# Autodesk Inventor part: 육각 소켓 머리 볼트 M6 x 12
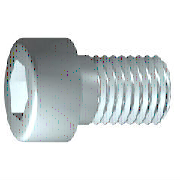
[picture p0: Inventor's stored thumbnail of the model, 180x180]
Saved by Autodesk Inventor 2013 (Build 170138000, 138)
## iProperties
IsCustomPart: 1
Created: 2012-02
Part Number: 육각 소켓 머리 볼트 M6 x 12
Material: 강철, 연강
Description: 원통형 머리 캡 나사
Document SubType Name: Modeling
Standard: JIS B 1176
Designer: mdu-01
Standards Organization: JIS
Language: ko-KR
Size Designation: M6 x 12
Categories: <MemberInstance><Categories><Category DisplayName="조임쇠" InternalName="e4da775c-781d-43d5-af7c-5136215cf5a6" Mnemonic="FSTN"><Category DisplayName="볼트" InternalN
Density: 1 g/cm^3
Author: mdu-01
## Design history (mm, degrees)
sketch "스케치1"
  geometry: L1 (-1.333, 0)-(12, 0); L2 (12, 0)-(12, 3); L3 (12, 3)-(2.5, 3); L4 (2.5, 3)-(1.886, 3); L5 (1.886, 3)-(0, 3); L6 (0, 3)-(0, 5); L7 (0, 5)-(-6, 5); L8 (-6, 5)-(-6, 2.887); L9 (-6, 2.887)-(-3, 2.887); L10 (-3, 2.887)-(-1.333, 0); L11 (-9.6, 0)-(15.6, 0) reference; L12 (0, -1)-(0, 6) reference; L13 (2.5, 3)-(0, 3)
  constraints: 22 end point, 6 parallel, 2 collinear, 2 perpendicular, 1 horizontal, 1 point on line
  dimensions: "d1" = 9.5 distance from line of L3.end L2 (= GEL); "d2" = 0.61355 distance of L4.end L3.end (computed from GAL); "d3" = 6 distance between parallel lines of L8 L6 (= KOH); "d4" = 3 distance of L8.end L9.end (= INTI); "d5" = 60 deg angle of L10 L1; "d6" = 6 diameter of L3 L1 (= GD); "d7" = 6 diameter of L5 L1 (= BDM); "d8" = 5.7735 diameter of L9 L1 (= 1.1547 x SW); "d9" = 10 diameter of L7 L1 (= KOD); "d26" = 12 distance between parallel lines of L12 L2 (= NLG)
revolve "본체" sketch "스케치1" stored, may be unused: angle "d10" = 90 deg
sketch "스케치2"
  geometry: L1 (0, -7)-(0, 7) reference; L2 (-7, 0)-(7, 0) reference; L3 (2.887, 0)-(1.443, -2.5); L4 (1.443, -2.5)-(-1.443, -2.5); L5 (-1.443, -2.5)-(-2.887, 0); L6 (-2.887, 0)-(-1.443, 2.5); L7 (-1.443, 2.5)-(1.443, 2.5); L8 (1.443, 2.5)-(2.887, 0); 2 further points
  constraints: 12 end point, 1 coincident, 1 horizontal alignment, 1 point on line, 12 other
extrude "슬롯" join sketch "스케치2" stored distance "d11" = 10; taper "d12" = 0 deg
workplane "Work Plane1"
fillet "Fillet2" dims "d30" = 0.1 (= R)
body "Solid1"
fillet "모깎기1" dims "d17" = 0.6 (= RR)
feature "스레드" dims "d13" = 9.5 (= GEL), "d14" = 0
chamfer "모따기1" distance "d15" = 0.61345 (= -0.5 x SPD + 0.5 x GD); stored, may be unused: second distance "d16" = 0.61345 (= GUL), angle "d27" = 45 deg
other parameters: "GD" = 6 (= NND) [user parameter; used in 2 equation terms], "NLG" = 12 [user parameter; used in 1 equation term], "GEL" = 9.5 [user parameter; used in 2 equation terms], "KOD" = 10 [user parameter; used in 1 equation term], "KOH" = 6 [user parameter; used in 1 equation term], "INTI" = 3 [user parameter; used in 1 equation term], "GAL" = 0.61345 (= 0.61345 x PTC) [user parameter; used in 1 equation term], "GUL" = 0.61345 (= 0.61345 x PTC) [user parameter; used in 1 equation term], "BDM" = 6 (= NND) [user parameter; used in 1 equation term], "SW" = 5 [user parameter; used in 2 equation terms], "RR" = 0.6 [user parameter; used in 1 equation term], "SPD" = 4.7731 (= NND - 1.2269 x PTC) [user parameter; used in 1 equation term], "d19" = 0, "d28" = 0, "d29" = 0, "R" = 0.1 [user parameter; used in 1 equation term], "PHH" = 0.25 [user parameter], "GD1" = 4.7731 (= THREADDIA - 1.2269 x PTC) [user parameter], "THREADDIA" = 6 [user parameter; used in 1 equation term], "FAWI" = 45 deg [user parameter], "PTC" = 1 [user parameter; used in 5 equation terms], "NND" = 6 [user parameter; used in 3 equation terms], "TOA" = 30 deg [user parameter], "E0" = 5.775 (= 1.155 x SW) [user parameter]
